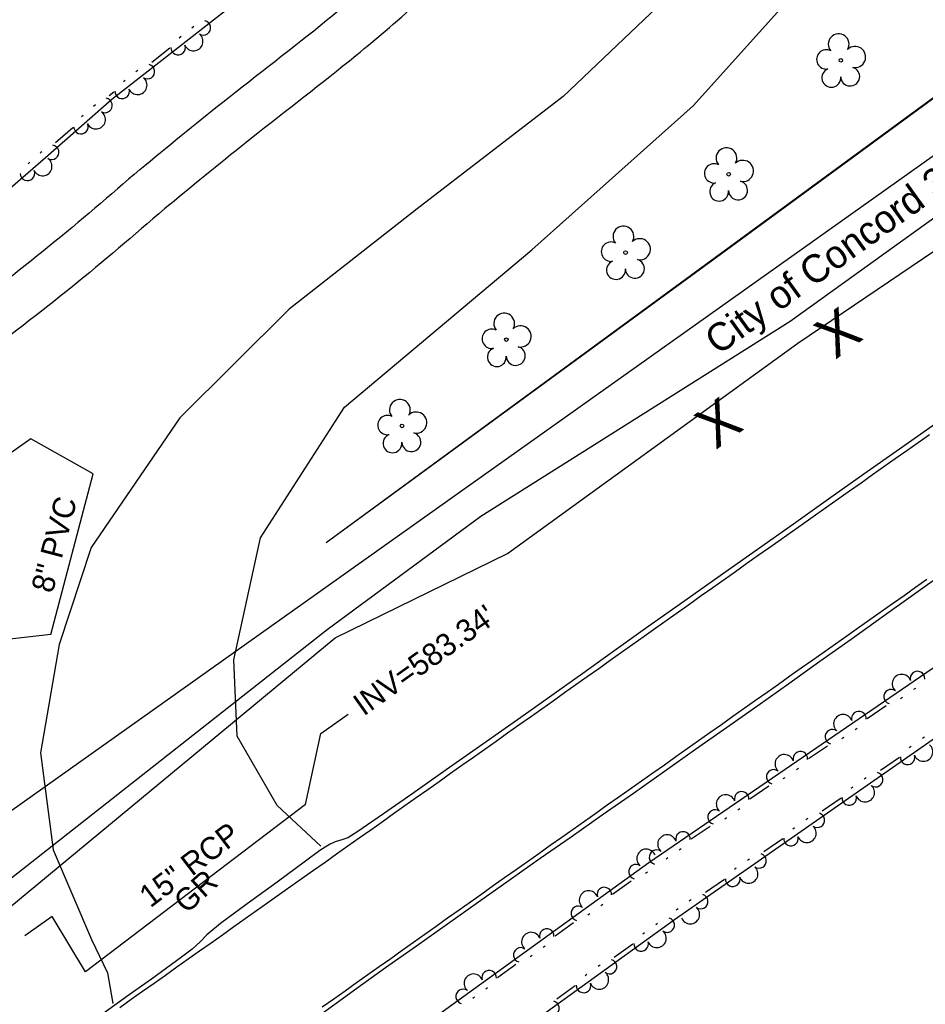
# Model space of a CAD drawing. Extents: x 1577032 to 1581865, y 611492 to 615011.
# Drawn here: x 1580788.7 to 1580950.8, y 614069.3 to 614245.5 of the extents above; entities that cross this region are included whole.
import ezdxf

# ---------------------------------------------------------------- set-up
doc = ezdxf.new("R2010")
doc.units = 0
for name, color, linetype in [('Exist Other Culture Fence Line', 7, 'Continuous'), ('Exist Right of Way Line', 7, 'Continuous'), ('Exist Roads EOP', 7, 'Continuous'), ('Exist Roads EOT', 7, 'Continuous'), ('Exist Roads Soil', 7, 'Continuous'), ('Exist Roads Soil Text', 7, 'Continuous'), ('Exist Structure Minor Pipes CMP 18 Inch Invert', 7, 'Continuous'), ('Exist Structure Minor Pipes CMP 18 Inch Leader', 7, 'Continuous'), ('Exist Structure Minor Pipes HDPE 8 Inch', 7, 'Continuous'), ('Exist Structure Minor Pipes HDPE 8 Inch Text', 7, 'Continuous'), ('Exist Structure Minor Pipes RCP 15 Inch', 7, 'Continuous'), ('Exist Structure Minor Pipes RCP 15 Inch Text', 7, 'Continuous'), ('Exist Utilities Telephone UG FO SUE LOS B', 7, 'Continuous'), ('Exist Utilities Water UG Line SUE LOS B', 7, 'Continuous'), ('Exist Utilities Water UG Line SUE LOS B Text', 7, 'Continuous'), ('Exist Vegetation Tree CELL', 7, 'Continuous'), ('Old_Level_11', 7, 'Continuous'), ('Scratch_Level_4', 7, 'Continuous')]:
    doc.layers.add(name, color=color, linetype=linetype)

msp = doc.modelspace()

# ---------------------------------------------------------------- linework, layer by layer
at = {"layer": 'Exist Other Culture Fence Line'}
for points in [[(1580843.54, 614151.95), (1580914.31, 614203.63), (1580981.96, 614253.3), (1581053.56, 614305.78), (1581115.1, 614350.96), (1581178.97, 614397.65), (1581213.26, 614422.92), (1581213.95, 614443.21), (1581207.27, 614448.89), (1581139.47, 614504.86)], [(1580843.54, 614151.95), (1581213.26, 614422.92), (1581213.95, 614443.21), (1581207.27, 614448.89), (1581139.47, 614504.86)], [(1580843.54, 614151.95), (1580914.31, 614203.63), (1580981.96, 614253.3), (1581053.56, 614305.78), (1581115.1, 614350.96), (1581178.97, 614397.65), (1581213.26, 614422.92), (1581213.95, 614443.21), (1581207.27, 614448.89)]]:
    msp.add_lwpolyline(points, dxfattribs=at)
at = {"layer": 'Exist Right of Way Line'}
msp.add_lwpolyline([(1580350.49, 613793.9), (1581560.23, 614652.99)], dxfattribs=at)
at = {"layer": 'Exist Roads EOP'}
for points in [[(1580952.58, 614173.17), (1580946.12, 614168.65), (1580939.75, 614164.16), (1580933.46, 614159.69), (1580927.19, 614155.25), (1580920.93, 614150.83), (1580914.49, 614146.3), (1580907.7, 614141.49), (1580900.72, 614136.55), (1580894.58, 614132.18), (1580889.45, 614128.51), (1580884.37, 614124.88), (1580878.36, 614120.62), (1580871.59, 614115.85), (1580865.04, 614111.25), (1580858.86, 614106.93), (1580853.81, 614103.39), (1580849.03, 614100.11), (1580847.41, 614099.12), (1580846.37, 614098.73), (1580845.19, 614098.37), (1580844.27, 614097.99), (1580843.37, 614097.46), (1580842.45, 614096.82), (1580839.87, 614094.92), (1580834.79, 614091.21), (1580829.4, 614087.3), (1580824.65, 614083.8), (1580822.19, 614081.74), (1580821.01, 614080.52), (1580819.6, 614079.22), (1580817.69, 614077.74), (1580812.28, 614073.84), (1580808.32, 614071), (1580803.62, 614067.64)], [(1580843.11, 614067.94), (1580848.65, 614071.94), (1580854.19, 614075.89), (1580859.72, 614079.81), (1580865.26, 614083.73), (1580870.79, 614087.65), (1580876.32, 614091.56), (1580881.86, 614095.45), (1580887.39, 614099.31), (1580892.95, 614103.2), (1580898.52, 614107.12), (1580904.09, 614111.05), (1580909.66, 614114.96), (1580915.21, 614118.87), (1580920.77, 614122.79), (1580926.33, 614126.74), (1580931.9, 614130.7), (1580937.48, 614134.67), (1580943.06, 614138.65), (1580948.64, 614142.64), (1580954.22, 614146.62)]]:
    msp.add_lwpolyline(points, dxfattribs=at)
at = {"layer": 'Exist Roads EOT'}
for points in [[(1580951.5, 614171.23), (1580949.46, 614169.78), (1580947.42, 614168.34), (1580945.37, 614166.9), (1580943.33, 614165.46), (1580941.29, 614164.02), (1580939.25, 614162.58), (1580937.2, 614161.14), (1580935.16, 614159.7), (1580933.12, 614158.26), (1580931.08, 614156.81), (1580929.04, 614155.37), (1580926.99, 614153.93), (1580924.95, 614152.49), (1580922.91, 614151.05), (1580920.87, 614149.61), (1580918.83, 614148.17), (1580916.79, 614146.72), (1580914.75, 614145.27), (1580912.71, 614143.83), (1580910.67, 614142.38), (1580908.63, 614140.94), (1580906.59, 614139.49), (1580904.56, 614138.05), (1580902.52, 614136.6), (1580900.48, 614135.15), (1580898.44, 614133.71), (1580896.4, 614132.26), (1580894.36, 614130.82), (1580892.32, 614129.37), (1580890.28, 614127.92), (1580888.25, 614126.48), (1580886.21, 614125.03), (1580884.17, 614123.59), (1580882.13, 614122.14), (1580880.09, 614120.7), (1580878.05, 614119.25), (1580876.01, 614117.81), (1580873.97, 614116.37), (1580871.93, 614114.92), (1580869.89, 614113.48), (1580867.85, 614112.04), (1580865.8, 614110.6), (1580863.76, 614109.15), (1580861.72, 614107.71), (1580859.68, 614106.27), (1580857.64, 614104.83), (1580855.6, 614103.38), (1580853.56, 614101.94), (1580851.52, 614100.5), (1580849.48, 614099.06), (1580847.43, 614097.62), (1580845.39, 614096.17), (1580843.35, 614094.73), (1580841.31, 614093.29), (1580839.27, 614091.85), (1580837.23, 614090.4), (1580835.19, 614088.96), (1580833.15, 614087.51), (1580831.11, 614086.07), (1580829.07, 614084.62), (1580827.03, 614083.18), (1580824.99, 614081.73), (1580822.96, 614080.29), (1580820.92, 614078.84), (1580818.88, 614077.4), (1580816.84, 614075.95), (1580814.8, 614074.51), (1580812.76, 614073.06), (1580810.72, 614071.62), (1580808.68, 614070.17), (1580806.64, 614068.73)], [(1580842.87, 614068.88), (1580844.91, 614070.32), (1580846.95, 614071.77), (1580848.99, 614073.21), (1580851.02, 614074.66), (1580853.06, 614076.11), (1580855.1, 614077.55), (1580857.14, 614079), (1580859.18, 614080.45), (1580861.22, 614081.89), (1580863.26, 614083.34), (1580865.29, 614084.78), (1580867.33, 614086.23), (1580869.37, 614087.68), (1580871.41, 614089.12), (1580873.45, 614090.56), (1580875.49, 614092.01), (1580877.53, 614093.45), (1580879.57, 614094.89), (1580881.61, 614096.33), (1580883.66, 614097.78), (1580885.7, 614099.22), (1580887.74, 614100.66), (1580889.78, 614102.1), (1580891.82, 614103.55), (1580893.86, 614104.99), (1580895.9, 614106.43), (1580897.94, 614107.87), (1580899.98, 614109.32), (1580902.03, 614110.76), (1580904.07, 614112.2), (1580906.11, 614113.64), (1580908.15, 614115.09), (1580910.19, 614116.53), (1580912.23, 614117.97), (1580914.27, 614119.41), (1580916.31, 614120.86), (1580918.35, 614122.3), (1580920.4, 614123.74), (1580922.44, 614125.18), (1580924.48, 614126.62), (1580926.52, 614128.07), (1580928.56, 614129.51), (1580930.6, 614130.95), (1580932.65, 614132.39), (1580934.69, 614133.83), (1580936.73, 614135.27), (1580938.77, 614136.72), (1580940.81, 614138.16), (1580942.85, 614139.6), (1580944.9, 614141.04), (1580946.94, 614142.48), (1580948.98, 614143.93), (1580951.02, 614145.37)]]:
    msp.add_lwpolyline(points, dxfattribs=at)
at = {"layer": 'Exist Roads Soil'}
for points in [[(1580947.25, 614319.05), (1580937.11, 614295.28), (1580922.28, 614270.62), (1580905.22, 614250.08), (1580885.95, 614231.74), (1580859.86, 614211.65), (1580836.93, 614193.69), (1580817.4, 614174.23), (1580801.52, 614151.03), (1580795.8, 614133.68), (1580792.46, 614114.3), (1580794.72, 614096.94), (1580801.59, 614080.9), (1580804.43, 614074.94), (1580805.4, 614069.46)], [(1580947.25, 614319.05), (1580937.11, 614295.28), (1580922.28, 614270.62), (1580905.22, 614250.08), (1580885.95, 614231.74), (1580859.86, 614211.65), (1580836.93, 614193.69), (1580817.4, 614174.23), (1580801.52, 614151.03), (1580795.8, 614133.68), (1580792.46, 614114.3), (1580794.72, 614096.94), (1580801.59, 614080.9), (1580804.43, 614074.94), (1580805.4, 614069.46)], [(1580842.62, 614097.61), (1580834.78, 614104.9), (1580827.64, 614117.28), (1580827.01, 614130.94), (1580831.8, 614152.77), (1580846.82, 614176.16), (1580880.36, 614204.32), (1580909.22, 614230.04), (1580934.52, 614258.19), (1580952.56, 614286.96), (1580963.08, 614312)], [(1580842.62, 614097.61), (1580834.78, 614104.9), (1580827.64, 614117.28), (1580827.01, 614130.94), (1580831.8, 614152.77), (1580846.82, 614176.16), (1580880.36, 614204.32), (1580909.22, 614230.04), (1580934.52, 614258.19), (1580952.56, 614286.96), (1580963.08, 614312)]]:
    msp.add_lwpolyline(points, dxfattribs=at)
at = {"layer": 'Exist Structure Minor Pipes CMP 18 Inch Leader'}
for points in [[(1580801.86, 614164.25), (1580790.71, 614170.51), (1580785.82, 614167.04)], [(1580794.27, 614135.48), (1580785.41, 614134.5), (1580780.52, 614131.03)], [(1580839.83, 614105.05), (1580842.58, 614117.78), (1580847.47, 614121.25)], [(1580800.5, 614075.15), (1580794.52, 614085.06), (1580789.63, 614081.59)]]:
    msp.add_lwpolyline(points, dxfattribs=at)
at = {"layer": 'Exist Structure Minor Pipes HDPE 8 Inch'}
msp.add_line((1580794.27, 614135.48), (1580801.86, 614164.25), dxfattribs=at)
msp.add_line((1580794.27, 614135.48), (1580801.86, 614164.25), dxfattribs=at)
at = {"layer": 'Exist Structure Minor Pipes RCP 15 Inch'}
msp.add_line((1580839.83, 614105.05), (1580800.5, 614075.15), dxfattribs=at)
msp.add_line((1580839.83, 614105.05), (1580800.5, 614075.15), dxfattribs=at)
at = {"layer": 'Exist Utilities Telephone UG FO SUE LOS B'}
msp.add_lwpolyline([(1580541.92, 613911.34), (1580565.99, 613928.5), (1580575.38, 613936.54), (1580607.26, 613958.8), (1580640.94, 613978.44), (1580673.15, 613998.31), (1580719.17, 614030.82), (1580788.35, 614087.85), (1580845.17, 614134.91), (1580876.01, 614149.96), (1580927.93, 614187.6), (1580984.72, 614225.98), (1580987.35, 614228.77), (1581072.57, 614287.71), (1581106.01, 614311.08), (1581124.14, 614323.41), (1581136.77, 614334.4), (1581140.56, 614340.68), (1581160.35, 614356.31), (1581239.56, 614412.21)], dxfattribs=at)
at = {"layer": 'Exist Utilities Water UG Line SUE LOS B'}
for p, q in [((1580926.56, 614191.54), (1580981.18, 614230.87)), ((1580871.21, 614156.63), (1580926.56, 614191.54)), ((1580843.74, 614136.36), (1580871.21, 614156.63)), ((1580785.6, 614090.67), (1580843.74, 614136.36))]:
    msp.add_line(p, q, dxfattribs=at)
at = {"layer": 'Exist Vegetation Tree CELL'}
for p, q in [((1580935.64, 614238.2), (1580935.64, 614238.2)), ((1580915.57, 614217.83), (1580915.57, 614217.83)), ((1580897.12, 614203.81), (1580897.12, 614203.81)), ((1580875.79, 614188.23), (1580875.79, 614188.23)), ((1580857.12, 614172.8), (1580857.12, 614172.8))]:
    msp.add_line(p, q, dxfattribs=at)
for centre in [(1580935.64, 614238.2), (1580915.57, 614217.83), (1580897.12, 614203.81), (1580875.79, 614188.23), (1580857.12, 614172.8)]:
    msp.add_circle(centre, 0.326, dxfattribs=at)
for centre, radius, start, end in [((1580935.25, 614241.08), 1.86, 330.1651, 219.7134), ((1580938.18, 614238.79), 1.9, 257.1011, 134.1999), ((1580933.03, 614238.36), 1.73, 62.6636, 279.3457), ((1580937.31, 614235.3), 1.7, 181.2822, 74.56), ((1580933.93, 614235.08), 1.69, 111.5671, 6.231), ((1580915.18, 614220.7), 1.86, 330.1651, 219.7134), ((1580912.96, 614217.98), 1.73, 62.6636, 279.3457), ((1580918.12, 614218.41), 1.9, 257.1011, 134.1999), ((1580913.86, 614214.71), 1.69, 111.5671, 6.231), ((1580917.24, 614214.93), 1.7, 181.2822, 74.56), ((1580896.74, 614206.69), 1.86, 330.1651, 219.7134), ((1580894.51, 614203.97), 1.73, 62.6636, 279.3457), ((1580899.67, 614204.4), 1.9, 257.1011, 134.1999), ((1580895.42, 614200.69), 1.69, 111.5671, 6.231), ((1580898.79, 614200.91), 1.7, 181.2822, 74.56), ((1580875.41, 614191.1), 1.86, 330.1651, 219.7134), ((1580873.19, 614188.38), 1.73, 62.6636, 279.3457), ((1580878.34, 614188.81), 1.9, 257.1011, 134.1999), ((1580874.09, 614185.11), 1.69, 111.5671, 6.231), ((1580877.47, 614185.33), 1.7, 181.2822, 74.56), ((1580856.74, 614175.67), 1.86, 330.1651, 219.7134), ((1580859.67, 614173.39), 1.9, 257.1011, 134.1999), ((1580854.52, 614172.95), 1.73, 62.6636, 279.3457), ((1580858.79, 614169.9), 1.7, 181.2822, 74.56), ((1580855.42, 614169.68), 1.69, 111.5671, 6.231)]:
    msp.add_arc(centre, radius, start, end, dxfattribs=at)
at = {"layer": 'Old_Level_11'}
for points in [[(1581076.08, 614559.89), (1581088.52, 614547.83), (1581100.64, 614534.14), (1581112.37, 614518.46), (1581110.88, 614504.93), (1581098.08, 614486.05), (1581066.09, 614457.4), (1581031.44, 614426.4), (1580993.03, 614392.77), (1580963.93, 614365.74), (1580907.09, 614321.77), (1580868.13, 614286.39), (1580834.77, 614254.31), (1580805.23, 614231.21)], [(1580819.86, 614244.22), (1580819.54, 614243.96)], [(1580817.6, 614242.45), (1580817.28, 614242.19)], [(1580815.59, 614240.36), (1580812.36, 614237.83)], [(1580809.85, 614236.38), (1580809.53, 614236.13)], [(1580807.59, 614234.61), (1580807.27, 614234.36)], [(1580805.58, 614232.52), (1580804.73, 614231.85)], [(1580805.23, 614231.21), (1580793.32, 614220.75), (1580777.46, 614207.05), (1580738.6, 614178.3), (1580714.44, 614161.19), (1580695.26, 614148.99), (1580670.75, 614138.7), (1580645.98, 614126.09), (1580618.93, 614113.06), (1580597.46, 614101.54), (1580588.5, 614095.99), (1580578.69, 614091.03), (1580573.78, 614091.38), (1580567.64, 614100.93), (1580576.73, 614123.22), (1580588.6, 614152.04), (1580595.77, 614169.54), (1580610.68, 614194.9)], [(1580802.26, 614230.24), (1580801.95, 614229.96)], [(1580800.11, 614228.34), (1580799.8, 614228.07)], [(1580798.22, 614226.14), (1580795.13, 614223.44)], [(1580792.71, 614221.85), (1580792.52, 614221.68), (1580792.41, 614221.59)], [(1580790.55, 614219.98), (1580790.23, 614219.71)], [(1580901.3, 614094.73), (1581025.18, 614179.49), (1581038.44, 614176.85), (1580905.9, 614084.46)], [(1580948.71, 614125.68), (1580949.04, 614125.91)], [(1580946.34, 614124.05), (1580946.68, 614124.29)], [(1580940.35, 614120.46), (1580943.74, 614122.77)], [(1580938.21, 614118.5), (1580938.55, 614118.73)], [(1580935.84, 614116.88), (1580936.18, 614117.11)], [(1580950.58, 614117.11), (1580950.25, 614116.88)], [(1580929.86, 614113.28), (1580933.24, 614115.59)], [(1580948.23, 614115.47), (1580947.89, 614115.23)], [(1580946.11, 614113.49), (1580942.74, 614111.15)], [(1580925.35, 614109.7), (1580925.69, 614109.93)], [(1580927.72, 614111.32), (1580928.06, 614111.55)], [(1580919.37, 614106.1), (1580922.75, 614108.41)], [(1580937.8, 614108.2), (1580937.46, 614107.96)], [(1580940.15, 614109.84), (1580939.82, 614109.61)], [(1580935.68, 614106.22), (1580932.31, 614103.88)], [(1580917.23, 614104.14), (1580917.57, 614104.37)], [(1580908.87, 614098.92), (1580912.26, 614101.23)], [(1580914.86, 614102.52), (1580915.2, 614102.75)], [(1580929.72, 614102.57), (1580929.39, 614102.33)], [(1580927.37, 614100.93), (1580927.03, 614100.69)], [(1580925.25, 614098.95), (1580921.88, 614096.6)], [(1580906.73, 614096.96), (1580907.07, 614097.19)], [(1580905.9, 614084.46), (1580765.09, 613982.83), (1580758.74, 613991.79), (1580901.3, 614094.73)], [(1580904.37, 614095.34), (1580904.71, 614095.57)], [(1580919.3, 614095.3), (1580918.96, 614095.07)], [(1580900.7, 614092.78), (1580901.03, 614093.02)], [(1580916.94, 614093.66), (1580916.6, 614093.42)], [(1580894.8, 614089.03), (1580898.13, 614091.43)], [(1580914.82, 614091.68), (1580911.45, 614089.33)], [(1580892.72, 614087.02), (1580893.05, 614087.26)], [(1580908.86, 614088.03), (1580908.53, 614087.79)], [(1580890.39, 614085.34), (1580890.72, 614085.58)], [(1580906.51, 614086.39), (1580906.17, 614086.15)], [(1580884.5, 614081.59), (1580887.82, 614083.99)], [(1580902.85, 614083.78), (1580902.52, 614083.54)], [(1580900.53, 614082.1), (1580900.19, 614081.86)], [(1580898.44, 614080.09), (1580895.11, 614077.69)], [(1580882.41, 614079.57), (1580882.74, 614079.82)], [(1580874.19, 614074.14), (1580877.52, 614076.54)], [(1580880.08, 614077.89), (1580880.42, 614078.13)], [(1580890.22, 614074.66), (1580889.88, 614074.42)], [(1580892.55, 614076.34), (1580892.21, 614076.1)], [(1580872.1, 614072.13), (1580872.44, 614072.37)], [(1580888.13, 614072.65), (1580884.8, 614070.25)], [(1580869.78, 614070.45), (1580870.11, 614070.69)]]:
    msp.add_lwpolyline(points, dxfattribs=at)
for centre, radius, start, end in [((1580821.59, 614244), 1.3, 236.4744, 77.2709), ((1580819.83, 614241.59), 1.69, 204.0032, 52.0757), ((1580817.07, 614240.47), 1.3, 178.8079, 19.6045), ((1580811.58, 614236.17), 1.3, 236.4744, 77.2709), ((1580809.82, 614233.76), 1.69, 204.0032, 52.0757), ((1580804, 614230.12), 1.3, 239.7074, 80.5039), ((1580807.06, 614232.63), 1.3, 178.8079, 19.6045), ((1580802.38, 614227.61), 1.69, 207.2362, 55.3087), ((1580799.68, 614226.34), 1.3, 182.0409, 22.8375), ((1580794.44, 614221.74), 1.3, 239.7074, 80.5039), ((1580792.81, 614219.23), 1.69, 206.7778, 54.8503), ((1580790.11, 614217.98), 1.3, 181.5826, 22.3791), ((1580946.53, 614126.67), 1.69, 20.3435, 228.416), ((1580949.36, 614127.62), 1.3, 355.1482, 195.9448), ((1580944.63, 614124.37), 1.3, 52.8147, 253.6113), ((1580936.04, 614119.49), 1.69, 20.3435, 228.416), ((1580938.87, 614120.44), 1.3, 355.1482, 195.9448), ((1580934.13, 614117.2), 1.3, 52.8147, 253.6113), ((1580950.41, 614114.49), 1.69, 200.8443, 48.9168), ((1580925.55, 614112.32), 1.69, 20.3435, 228.416), ((1580928.38, 614113.26), 1.3, 355.1482, 195.9448), ((1580947.59, 614113.52), 1.3, 175.6491, 16.4456), ((1580923.64, 614110.02), 1.3, 52.8147, 253.6113), ((1580941.87, 614109.53), 1.3, 233.3155, 74.1121), ((1580939.98, 614107.22), 1.69, 200.8443, 48.9168), ((1580915.05, 614105.14), 1.69, 20.3435, 228.416), ((1580917.89, 614106.08), 1.3, 355.1482, 195.9448), ((1580937.16, 614106.25), 1.3, 175.6491, 16.4456), ((1580913.15, 614102.84), 1.3, 52.8147, 253.6113), ((1580931.44, 614102.26), 1.3, 233.3155, 74.1121), ((1580929.55, 614099.95), 1.69, 200.8443, 48.9168), ((1580904.56, 614097.96), 1.69, 20.3435, 228.416), ((1580907.39, 614098.9), 1.3, 355.1482, 195.9448), ((1580926.73, 614098.98), 1.3, 175.6491, 16.4456), ((1580900.83, 614095.4), 1.69, 21.7962, 229.8687), ((1580902.66, 614095.66), 1.3, 52.8147, 253.6113), ((1580921.01, 614094.99), 1.3, 233.3155, 74.1121), ((1580898.98, 614093.06), 1.3, 54.2674, 255.064), ((1580919.12, 614092.68), 1.69, 200.8443, 48.9168), ((1580916.3, 614091.71), 1.3, 175.6491, 16.4456), ((1580890.52, 614087.96), 1.69, 21.7962, 229.8687), ((1580893.33, 614088.97), 1.3, 356.6009, 197.3975), ((1580910.58, 614087.72), 1.3, 233.3155, 74.1121), ((1580888.67, 614085.61), 1.3, 54.2674, 255.064), ((1580908.69, 614085.41), 1.69, 200.8443, 48.9168), ((1580904.57, 614083.5), 1.3, 234.256, 75.0526), ((1580880.21, 614080.52), 1.69, 21.7962, 229.8687), ((1580883.02, 614081.53), 1.3, 356.6009, 197.3975), ((1580902.72, 614081.16), 1.69, 201.7848, 49.8573), ((1580899.91, 614080.14), 1.3, 176.5895, 17.3861), ((1580878.37, 614078.17), 1.3, 54.2674, 255.064), ((1580894.26, 614076.06), 1.3, 234.256, 75.0526), ((1580869.91, 614073.07), 1.69, 21.7962, 229.8687), ((1580872.71, 614074.09), 1.3, 356.6009, 197.3975), ((1580892.41, 614073.72), 1.69, 201.7848, 49.8573), ((1580889.61, 614072.7), 1.3, 176.5895, 17.3861), ((1580868.06, 614070.73), 1.3, 54.2674, 255.064), ((1580883.95, 614068.62), 1.3, 234.256, 75.0526)]:
    msp.add_arc(centre, radius, start, end, dxfattribs=at)
at = {"layer": 'Scratch_Level_4'}
for points in [[(1580810.22, 614218.65), (1580825.05, 614230.72), (1580843.62, 614245.36), (1580866.82, 614265.83), (1580900.47, 614296.36), (1580933.43, 614323.08), (1580959.89, 614345.31), (1580984.67, 614368.02), (1581015.29, 614393.59), (1581049.92, 614423.64), (1581082.64, 614453.16), (1581106.95, 614476.82), (1581123.61, 614498.18), (1581131.45, 614509.84)], [(1580815.44, 614212.32), (1580830.18, 614224.32), (1580848.88, 614239.06), (1580872.29, 614259.72), (1580905.81, 614290.13), (1580938.65, 614316.75), (1580965.3, 614339.14), (1580990.07, 614361.84), (1581020.61, 614387.35), (1581055.35, 614417.49), (1581088.25, 614447.18), (1581113.07, 614471.33), (1581130.26, 614493.37), (1581138.39, 614505.46)], [(1580810.22, 614218.65), (1580794.01, 614204.94), (1580776.63, 614191.46), (1580758.52, 614178.29), (1580738.37, 614164.68), (1580712.29, 614150.98), (1580696.94, 614143.92), (1580679.7, 614135.59), (1580659.13, 614126.84), (1580639.58, 614117.59), (1580624.68, 614110.07), (1580609.66, 614101.2), (1580587.29, 614087.37), (1580579.96, 614081.01), (1580573.74, 614079.45), (1580566.21, 614084.89), (1580558.85, 614093.55), (1580547.54, 614104.99), (1580534.62, 614117.27), (1580522.93, 614130.96), (1580516.2, 614138.44)], [(1580815.64, 614212.49), (1580799.17, 614198.56), (1580781.56, 614184.9), (1580763.22, 614171.57), (1580742.59, 614157.63), (1580715.91, 614143.62), (1580708.96, 614140.42)]]:
    msp.add_spline(points, degree=3, dxfattribs=at)

# ---------------------------------------------------------------- texts
at = {"layer": 'Exist Roads Soil Text'}
msp.add_text('GR', height=4, rotation=42.2938, dxfattribs=at).set_placement((1580818.59, 614085.4))
at = {"layer": 'Exist Structure Minor Pipes CMP 18 Inch Invert'}
msp.add_text("INV=583.34'", height=4, rotation=35.38, dxfattribs=at).set_placement((1580850.26, 614120.78))
at = {"layer": 'Exist Structure Minor Pipes HDPE 8 Inch Text'}
msp.add_text('8" PVC', height=4, rotation=75.2278, dxfattribs=at).set_placement((1580794.6, 614142.71))
at = {"layer": 'Exist Structure Minor Pipes RCP 15 Inch Text'}
msp.add_text('15" RCP', height=4, rotation=37.2428, dxfattribs=at).set_placement((1580812.1, 614086.48))
at = {"layer": 'Exist Utilities Water UG Line SUE LOS B Text'}
msp.add_text('City of Concord 30" DIP', height=5, rotation=35.7637, dxfattribs=at).set_placement((1580913.68, 614185.34))
at = {"layer": 'Exist Vegetation Tree CELL'}
for p in [(1580934.59, 614184.57), (1580913.22, 614168.44)]:
    msp.add_text('X', height=7.38, rotation=36.0651, dxfattribs=at).set_placement(p)

doc.saveas('drawing.dxf')
